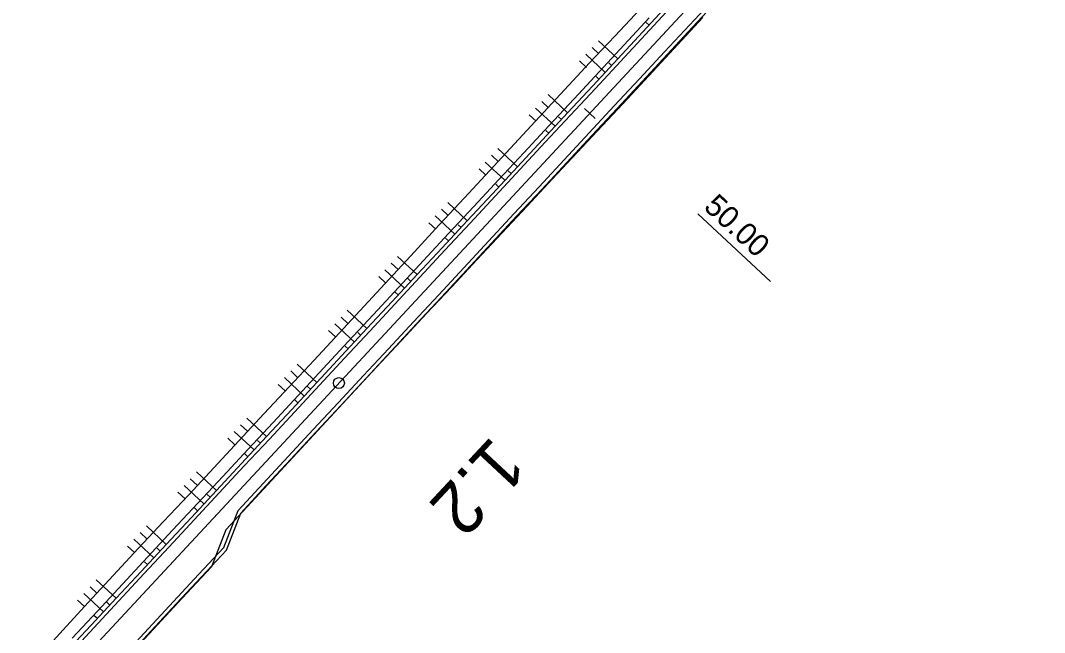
# Model space of a CAD drawing. Extents: x -481645 to -478728, y -1113199 to -1110710.
# Drawn here: x -479136.3 to -478997.3, y -1110940.2 to -1110857.1 of the extents above; entities that cross this region are included whole.
import ezdxf

# ---------------------------------------------------------------- set-up
doc = ezdxf.new("R2010")
doc.units = 0
for name, color, linetype in [('CP14_HATCH_SLOPE_L', 7, 'Continuous'), ('CP1_HECTOMETRY', 7, 'Continuous'), ('O6_HATCH_SLOPE_L', 7, 'Continuous'), ('O6_HATCH_SLOPE_R', 7, 'Continuous'), ('O6_HLBODY', 7, 'Continuous'), ('O6_HRANA_TELESO', 7, 'Continuous'), ('O6_OSA', 7, 'Continuous'), ('O6_VOZOVKA', 7, 'Continuous'), ('O6_ZPEVKRAJ', 7, 'Continuous')]:
    doc.layers.add(name, color=color, linetype=linetype)

msp = doc.modelspace()

# ---------------------------------------------------------------- linework, layer by layer
at = {"layer": 'CP14_HATCH_SLOPE_L'}
for p, q in [((-479047.12, -1110860.26), (-479047.03, -1110860.35)), ((-479047.98, -1110861.18), (-479047.93, -1110861.22)), ((-479047.88, -1110861.27), (-479047.88, -1110861.27)), ((-479049.68, -1110863.01), (-479049.63, -1110863.06)), ((-479049.58, -1110863.1), (-479049.58, -1110863.1)), ((-479048.83, -1110862.09), (-479048.73, -1110862.19)), ((-479053.93, -1110867.58), (-479053.83, -1110867.69)), ((-479054.79, -1110868.5), (-479054.73, -1110868.55)), ((-479054.68, -1110868.6), (-479054.68, -1110868.6)), ((-479056.49, -1110870.33), (-479056.44, -1110870.38)), ((-479055.64, -1110869.42), (-479055.53, -1110869.51)), ((-479056.39, -1110870.43), (-479056.39, -1110870.43)), ((-479061.6, -1110875.82), (-479061.55, -1110875.86)), ((-479061.51, -1110875.9), (-479061.51, -1110875.9)), ((-479060.74, -1110874.91), (-479060.66, -1110874.99)), ((-479062.45, -1110876.74), (-479062.36, -1110876.82)), ((-479063.3, -1110877.65), (-479063.26, -1110877.69)), ((-479063.22, -1110877.73), (-479063.22, -1110877.73)), ((-479067.55, -1110882.23), (-479067.49, -1110882.29)), ((-479069.26, -1110884.06), (-479069.19, -1110884.12)), ((-479068.41, -1110883.15), (-479068.37, -1110883.18)), ((-479068.34, -1110883.21), (-479068.34, -1110883.21)), ((-479070.11, -1110884.98), (-479070.08, -1110885)), ((-479070.05, -1110885.03), (-479070.05, -1110885.03)), ((-479074.36, -1110889.55), (-479074.32, -1110889.6)), ((-479075.22, -1110890.47), (-479075.19, -1110890.49)), ((-479075.17, -1110890.51), (-479075.17, -1110890.51)), ((-479076.92, -1110892.3), (-479076.9, -1110892.32)), ((-479076.88, -1110892.34), (-479076.88, -1110892.34)), ((-479076.07, -1110891.38), (-479076.02, -1110891.43)), ((-479082.03, -1110897.79), (-479082.01, -1110897.8)), ((-479082, -1110897.82), (-479082, -1110897.82)), ((-479081.17, -1110896.88), (-479081.15, -1110896.9)), ((-479082.88, -1110898.71), (-479082.85, -1110898.73)), ((-479083.73, -1110899.62), (-479083.72, -1110899.63)), ((-479083.71, -1110899.64), (-479083.71, -1110899.64)), ((-479088.84, -1110905.11), (-479088.83, -1110905.12)), ((-479088.82, -1110905.13), (-479088.82, -1110905.13)), ((-479087.98, -1110904.2), (-479087.97, -1110904.22)), ((-479089.69, -1110906.03), (-479089.67, -1110906.05)), ((-479090.54, -1110906.95), (-479090.53, -1110906.96)), ((-479090.52, -1110906.97), (-479090.52, -1110906.97)), ((-479094.79, -1110911.52), (-479094.77, -1110911.55)), ((-479096.5, -1110913.35), (-479096.47, -1110913.38)), ((-479095.65, -1110912.44), (-479095.63, -1110912.45)), ((-479095.62, -1110912.47), (-479095.62, -1110912.47)), ((-479097.35, -1110914.27), (-479097.33, -1110914.28)), ((-479097.32, -1110914.3), (-479097.32, -1110914.3)), ((-479101.6, -1110918.84), (-479101.56, -1110918.88)), ((-479102.46, -1110919.76), (-479102.43, -1110919.78)), ((-479102.41, -1110919.8), (-479102.41, -1110919.8)), ((-479104.16, -1110921.59), (-479104.14, -1110921.61)), ((-479104.11, -1110921.63), (-479104.11, -1110921.63)), ((-479103.31, -1110920.68), (-479103.26, -1110920.72)), ((-479108.41, -1110926.17), (-479108.36, -1110926.21)), ((-479109.38, -1110928.68), (-479109.33, -1110928.73)), ((-479108.9, -1110927.42), (-479108.87, -1110927.45)), ((-479108.85, -1110927.47), (-479108.85, -1110927.47)), ((-479109.87, -1110929.94), (-479109.84, -1110929.96)), ((-479109.82, -1110929.98), (-479109.82, -1110929.98)), ((-479113.76, -1110934.85), (-479113.71, -1110934.9)), ((-479115.46, -1110936.68), (-479115.41, -1110936.74)), ((-479114.61, -1110935.77), (-479114.58, -1110935.79)), ((-479114.56, -1110935.82), (-479114.56, -1110935.82)), ((-479116.31, -1110937.6), (-479116.28, -1110937.63)), ((-479116.26, -1110937.65), (-479116.26, -1110937.65))]:
    msp.add_line(p, q, dxfattribs=at)
at = {"layer": 'CP1_HECTOMETRY'}
msp.add_line((-479231.87, -1111055.62), (-478997.26, -1110803.33), dxfattribs=at)
at = {"layer": 'O6_HATCH_SLOPE_L'}
msp.add_circle((-479093.04, -1110906.33), 0.75, dxfattribs=at)
at = {"layer": 'O6_HATCH_SLOPE_R'}
for p, q in [((-479050.93, -1110857.74), (-479051.31, -1110857.38)), ((-479055.18, -1110862.32), (-479057.82, -1110859.86)), ((-479056.88, -1110864.15), (-479059.53, -1110861.69)), ((-479057.75, -1110861.64), (-479058.68, -1110860.77)), ((-479059.45, -1110863.47), (-479060.39, -1110862.6)), ((-479056.03, -1110863.23), (-479056.42, -1110862.87)), ((-479057.74, -1110865.06), (-479058.13, -1110864.7)), ((-479061.99, -1110869.64), (-479064.65, -1110867.17)), ((-479063.69, -1110871.47), (-479066.35, -1110869)), ((-479064.57, -1110868.95), (-479065.5, -1110868.08)), ((-479066.27, -1110870.78), (-479067.21, -1110869.91)), ((-479062.84, -1110870.56), (-479063.24, -1110870.19)), ((-479064.55, -1110872.39), (-479064.94, -1110872.02)), ((-479068.8, -1110876.96), (-479071.46, -1110874.49)), ((-479071.38, -1110876.27), (-479072.31, -1110875.4)), ((-479073.08, -1110878.1), (-479074.02, -1110877.24)), ((-479070.5, -1110878.79), (-479073.17, -1110876.32)), ((-479069.65, -1110877.88), (-479070.05, -1110877.51)), ((-479071.35, -1110879.71), (-479071.75, -1110879.34)), ((-479078.19, -1110883.59), (-479079.12, -1110882.73)), ((-479075.61, -1110884.29), (-479078.27, -1110881.81)), ((-479077.31, -1110886.12), (-479079.98, -1110883.64)), ((-479079.89, -1110885.42), (-479080.83, -1110884.56)), ((-479076.46, -1110885.2), (-479076.86, -1110884.83)), ((-479078.17, -1110887.03), (-479078.56, -1110886.66)), ((-479082.42, -1110891.61), (-479085.08, -1110889.13)), ((-479084.12, -1110893.44), (-479086.79, -1110890.96)), ((-479085, -1110890.91), (-479085.94, -1110890.05)), ((-479086.71, -1110892.74), (-479087.64, -1110891.88)), ((-479083.27, -1110892.52), (-479083.67, -1110892.15)), ((-479084.98, -1110894.35), (-479085.38, -1110893.98)), ((-479089.23, -1110898.93), (-479091.9, -1110896.45)), ((-479091.82, -1110898.23), (-479092.75, -1110897.37)), ((-479093.52, -1110900.06), (-479094.46, -1110899.2)), ((-479090.93, -1110900.76), (-479093.6, -1110898.28)), ((-479090.08, -1110899.85), (-479090.48, -1110899.47)), ((-479091.79, -1110901.68), (-479092.19, -1110901.3)), ((-479096.04, -1110906.26), (-479098.72, -1110903.77)), ((-479098.64, -1110905.55), (-479099.57, -1110904.68)), ((-479100.34, -1110907.38), (-479101.28, -1110906.51)), ((-479097.74, -1110908.09), (-479100.42, -1110905.59)), ((-479096.89, -1110907.17), (-479097.3, -1110906.79)), ((-479098.6, -1110909), (-479099, -1110908.62)), ((-479105.46, -1110912.86), (-479106.39, -1110911.99)), ((-479102.85, -1110913.58), (-479105.54, -1110911.08)), ((-479104.55, -1110915.41), (-479107.24, -1110912.91)), ((-479107.16, -1110914.69), (-479108.1, -1110913.82)), ((-479103.7, -1110914.49), (-479104.11, -1110914.11)), ((-479105.41, -1110916.32), (-479105.81, -1110915.94)), ((-479109.66, -1110920.9), (-479112.36, -1110918.39)), ((-479111.36, -1110922.73), (-479114.06, -1110920.22)), ((-479112.27, -1110920.18), (-479113.21, -1110919.31)), ((-479113.97, -1110922.01), (-479114.91, -1110921.14)), ((-479110.51, -1110921.82), (-479110.92, -1110921.44)), ((-479112.22, -1110923.65), (-479112.62, -1110923.27)), ((-479116.47, -1110928.22), (-479119.17, -1110925.71)), ((-479119.08, -1110927.51), (-479120.02, -1110926.63)), ((-479120.78, -1110929.34), (-479121.72, -1110928.46)), ((-479118.17, -1110930.05), (-479120.87, -1110927.54)), ((-479117.32, -1110929.14), (-479117.73, -1110928.76)), ((-479119.02, -1110930.97), (-479119.43, -1110930.59)), ((-479125.88, -1110934.84), (-479126.82, -1110933.97)), ((-479123.28, -1110935.55), (-479125.97, -1110933.04)), ((-479124.98, -1110937.38), (-479127.66, -1110934.89)), ((-479127.58, -1110936.67), (-479128.51, -1110935.81)), ((-479124.13, -1110936.46), (-479124.54, -1110936.09)), ((-479125.83, -1110938.29), (-479126.24, -1110937.92))]:
    msp.add_line(p, q, dxfattribs=at)
at = {"layer": 'O6_HLBODY'}
for p, q in [((-479058.26, -1110870.4), (-479059.72, -1110869.03)), ((-479044.34, -1110883.33), (-479034.46, -1110892.53))]:
    msp.add_line(p, q, dxfattribs=at)
at = {"layer": 'O6_HRANA_TELESO'}
for p, q in [((-479054.31, -1110860.41), (-479050.91, -1110856.74)), ((-479057.72, -1110864.07), (-479054.31, -1110860.41)), ((-479061.12, -1110867.73), (-479057.72, -1110864.07)), ((-479064.53, -1110871.39), (-479061.12, -1110867.73)), ((-479067.93, -1110875.05), (-479064.53, -1110871.39)), ((-479071.34, -1110878.71), (-479067.93, -1110875.05)), ((-479074.74, -1110882.37), (-479071.34, -1110878.71)), ((-479078.15, -1110886.03), (-479074.74, -1110882.37)), ((-479081.55, -1110889.7), (-479078.15, -1110886.03)), ((-479084.96, -1110893.36), (-479081.55, -1110889.7)), ((-479088.36, -1110897.02), (-479084.96, -1110893.36)), ((-479091.77, -1110900.68), (-479088.36, -1110897.02)), ((-479095.17, -1110904.34), (-479091.77, -1110900.68)), ((-479098.58, -1110908), (-479095.17, -1110904.34)), ((-479101.98, -1110911.67), (-479098.58, -1110908)), ((-479105.39, -1110915.33), (-479101.98, -1110911.67)), ((-479108.79, -1110918.99), (-479105.39, -1110915.33)), ((-479112.2, -1110922.65), (-479108.79, -1110918.99)), ((-479115.61, -1110926.3), (-479112.2, -1110922.65)), ((-479119.02, -1110929.97), (-479115.61, -1110926.3)), ((-479122.42, -1110933.63), (-479119.02, -1110929.97)), ((-479125.83, -1110937.29), (-479122.42, -1110933.63)), ((-479129.23, -1110940.95), (-479125.83, -1110937.29))]:
    msp.add_line(p, q, dxfattribs=at)
at = {"layer": 'O6_OSA'}
for p, q in [((-479055.59, -1110859.22), (-479052.16, -1110855.58)), ((-479047.03, -1110860.35), (-479043.62, -1110856.69)), ((-479059.02, -1110862.86), (-479055.59, -1110859.22)), ((-479050.43, -1110864.02), (-479047.03, -1110860.35)), ((-479062.42, -1110866.52), (-479059.02, -1110862.86)), ((-479053.83, -1110867.69), (-479050.43, -1110864.02)), ((-479065.82, -1110870.19), (-479062.42, -1110866.52)), ((-479057.24, -1110871.34), (-479053.83, -1110867.69)), ((-479069.21, -1110873.86), (-479065.82, -1110870.19)), ((-479060.66, -1110874.99), (-479057.24, -1110871.34)), ((-479072.61, -1110877.53), (-479069.21, -1110873.86)), ((-479064.07, -1110878.64), (-479060.66, -1110874.99)), ((-479076.01, -1110881.2), (-479072.61, -1110877.53)), ((-479067.49, -1110882.29), (-479064.07, -1110878.64)), ((-479079.41, -1110884.86), (-479076.01, -1110881.2)), ((-479070.9, -1110885.95), (-479067.49, -1110882.29)), ((-479082.8, -1110888.53), (-479079.41, -1110884.86)), ((-479074.32, -1110889.6), (-479070.9, -1110885.95)), ((-479086.2, -1110892.2), (-479082.8, -1110888.53)), ((-479077.73, -1110893.25), (-479074.32, -1110889.6)), ((-479089.6, -1110895.87), (-479086.2, -1110892.2)), ((-479081.15, -1110896.9), (-479077.73, -1110893.25)), ((-479093, -1110899.53), (-479089.6, -1110895.87)), ((-479084.56, -1110900.55), (-479081.15, -1110896.9)), ((-479096.41, -1110903.2), (-479093, -1110899.53)), ((-479087.97, -1110904.22), (-479084.56, -1110900.55)), ((-479099.81, -1110906.86), (-479096.41, -1110903.2)), ((-479091.37, -1110907.88), (-479087.97, -1110904.22)), ((-479103.21, -1110910.52), (-479099.81, -1110906.86)), ((-479094.77, -1110911.55), (-479091.37, -1110907.88)), ((-479106.61, -1110914.19), (-479103.21, -1110910.52)), ((-479098.17, -1110915.22), (-479094.77, -1110911.55)), ((-479110.02, -1110917.85), (-479106.61, -1110914.19)), ((-479101.56, -1110918.88), (-479098.17, -1110915.22)), ((-479113.43, -1110921.5), (-479110.02, -1110917.85)), ((-479104.96, -1110922.55), (-479101.56, -1110918.88)), ((-479116.86, -1110925.14), (-479113.43, -1110921.5)), ((-479108.36, -1110926.21), (-479104.96, -1110922.55)), ((-479120.27, -1110928.79), (-479116.86, -1110925.14)), ((-479110.3, -1110931.24), (-479108.36, -1110926.21)), ((-479123.68, -1110932.45), (-479120.27, -1110928.79)), ((-479113.71, -1110934.9), (-479110.3, -1110931.24)), ((-479127.07, -1110936.13), (-479123.68, -1110932.45)), ((-479117.11, -1110938.57), (-479113.71, -1110934.9)), ((-479130.46, -1110939.81), (-479127.07, -1110936.13)), ((-479133.82, -1110943.51), (-479130.46, -1110939.81)), ((-479120.5, -1110942.24), (-479117.11, -1110938.57))]:
    msp.add_line(p, q, dxfattribs=at)
at = {"layer": 'O6_VOZOVKA'}
for p, q in [((-479045.44, -1110857.72), (-479042.04, -1110854.06)), ((-479051.41, -1110859), (-479048.01, -1110855.33)), ((-479048.85, -1110861.38), (-479045.44, -1110857.72)), ((-479054.82, -1110862.66), (-479051.41, -1110859)), ((-479052.25, -1110865.04), (-479048.85, -1110861.38)), ((-479058.22, -1110866.32), (-479054.82, -1110862.66)), ((-479055.66, -1110868.7), (-479052.25, -1110865.04)), ((-479061.63, -1110869.98), (-479058.22, -1110866.32)), ((-479059.06, -1110872.36), (-479055.66, -1110868.7)), ((-479065.03, -1110873.64), (-479061.63, -1110869.98)), ((-479062.47, -1110876.03), (-479059.06, -1110872.36)), ((-479068.44, -1110877.3), (-479065.03, -1110873.64)), ((-479071.84, -1110880.97), (-479068.44, -1110877.3)), ((-479065.87, -1110879.69), (-479062.47, -1110876.03)), ((-479069.28, -1110883.35), (-479065.87, -1110879.69)), ((-479075.24, -1110884.63), (-479071.84, -1110880.97)), ((-479072.68, -1110887.01), (-479069.28, -1110883.35)), ((-479078.65, -1110888.29), (-479075.24, -1110884.63)), ((-479076.09, -1110890.67), (-479072.68, -1110887.01)), ((-479082.05, -1110891.95), (-479078.65, -1110888.29)), ((-479079.49, -1110894.33), (-479076.09, -1110890.67)), ((-479085.46, -1110895.61), (-479082.05, -1110891.95)), ((-479082.9, -1110898), (-479079.49, -1110894.33)), ((-479088.86, -1110899.27), (-479085.46, -1110895.61)), ((-479086.3, -1110901.66), (-479082.9, -1110898)), ((-479092.27, -1110902.93), (-479088.86, -1110899.27)), ((-479089.71, -1110905.32), (-479086.3, -1110901.66)), ((-479095.67, -1110906.6), (-479092.27, -1110902.93)), ((-479093.11, -1110908.98), (-479089.71, -1110905.32)), ((-479099.08, -1110910.26), (-479095.67, -1110906.6)), ((-479096.52, -1110912.64), (-479093.11, -1110908.98)), ((-479102.48, -1110913.92), (-479099.08, -1110910.26)), ((-479099.92, -1110916.3), (-479096.52, -1110912.64)), ((-479105.89, -1110917.58), (-479102.48, -1110913.92)), ((-479109.29, -1110921.24), (-479105.89, -1110917.58)), ((-479103.33, -1110919.96), (-479099.92, -1110916.3)), ((-479106.73, -1110923.62), (-479103.33, -1110919.96)), ((-479112.7, -1110924.9), (-479109.29, -1110921.24)), ((-479108.67, -1110928.65), (-479106.73, -1110923.62)), ((-479116.1, -1110928.56), (-479112.7, -1110924.9)), ((-479119.51, -1110932.23), (-479116.1, -1110928.56)), ((-479112.08, -1110932.31), (-479108.67, -1110928.65)), ((-479122.91, -1110935.89), (-479119.51, -1110932.23)), ((-479115.48, -1110935.97), (-479112.08, -1110932.31)), ((-479126.32, -1110939.55), (-479122.91, -1110935.89)), ((-479118.89, -1110939.63), (-479115.48, -1110935.97)), ((-479129.72, -1110943.21), (-479126.32, -1110939.55)), ((-479122.29, -1110943.29), (-479118.89, -1110939.63))]:
    msp.add_line(p, q, dxfattribs=at)
at = {"layer": 'O6_ZPEVKRAJ'}
for p, q in [((-479051.78, -1110858.66), (-479048.37, -1110854.99)), ((-479045.08, -1110858.06), (-479041.67, -1110854.4)), ((-479055.18, -1110862.32), (-479051.78, -1110858.66)), ((-479048.48, -1110861.72), (-479045.08, -1110858.06)), ((-479051.89, -1110865.38), (-479048.48, -1110861.72)), ((-479058.59, -1110865.98), (-479055.18, -1110862.32)), ((-479061.99, -1110869.64), (-479058.59, -1110865.98)), ((-479055.29, -1110869.04), (-479051.89, -1110865.38)), ((-479065.4, -1110873.3), (-479061.99, -1110869.64)), ((-479058.7, -1110872.71), (-479055.29, -1110869.04)), ((-479062.1, -1110876.37), (-479058.7, -1110872.71)), ((-479068.8, -1110876.96), (-479065.4, -1110873.3)), ((-479072.21, -1110880.62), (-479068.8, -1110876.96)), ((-479065.51, -1110880.03), (-479062.1, -1110876.37)), ((-479068.91, -1110883.69), (-479065.51, -1110880.03)), ((-479075.61, -1110884.29), (-479072.21, -1110880.62)), ((-479079.02, -1110887.95), (-479075.61, -1110884.29)), ((-479072.32, -1110887.35), (-479068.91, -1110883.69)), ((-479082.42, -1110891.61), (-479079.02, -1110887.95)), ((-479075.72, -1110891.01), (-479072.32, -1110887.35)), ((-479079.13, -1110894.67), (-479075.72, -1110891.01)), ((-479085.83, -1110895.27), (-479082.42, -1110891.61)), ((-479089.23, -1110898.93), (-479085.83, -1110895.27)), ((-479082.53, -1110898.33), (-479079.13, -1110894.67)), ((-479092.64, -1110902.59), (-479089.23, -1110898.93)), ((-479085.94, -1110902), (-479082.53, -1110898.33)), ((-479089.34, -1110905.66), (-479085.94, -1110902)), ((-479096.04, -1110906.26), (-479092.64, -1110902.59)), ((-479099.45, -1110909.92), (-479096.04, -1110906.26)), ((-479092.75, -1110909.32), (-479089.34, -1110905.66)), ((-479096.15, -1110912.98), (-479092.75, -1110909.32)), ((-479102.85, -1110913.58), (-479099.45, -1110909.92)), ((-479099.56, -1110916.64), (-479096.15, -1110912.98)), ((-479106.26, -1110917.24), (-479102.85, -1110913.58)), ((-479109.66, -1110920.9), (-479106.26, -1110917.24)), ((-479102.96, -1110920.3), (-479099.56, -1110916.64)), ((-479106.37, -1110923.97), (-479102.96, -1110920.3)), ((-479113.07, -1110924.56), (-479109.66, -1110920.9)), ((-479116.47, -1110928.22), (-479113.07, -1110924.56)), ((-479108.31, -1110928.99), (-479106.37, -1110923.97)), ((-479119.88, -1110931.89), (-479116.47, -1110928.22)), ((-479111.71, -1110932.65), (-479108.31, -1110928.99)), ((-479123.28, -1110935.55), (-479119.88, -1110931.89)), ((-479115.12, -1110936.31), (-479111.71, -1110932.65)), ((-479126.69, -1110939.21), (-479123.28, -1110935.55)), ((-479118.52, -1110939.97), (-479115.12, -1110936.31)), ((-479130.09, -1110942.87), (-479126.69, -1110939.21)), ((-479121.93, -1110943.64), (-479118.52, -1110939.97))]:
    msp.add_line(p, q, dxfattribs=at)

# ---------------------------------------------------------------- texts
at = {"layer": 'O6_HATCH_SLOPE_L'}
msp.add_text('1.2', height=7, rotation=227.0337, dxfattribs=at).set_placement((-479072.23, -1110913.33))
at = {"layer": 'O6_HLBODY'}
msp.add_text('50.00', height=2.999, rotation=317.0793, dxfattribs=at).set_placement((-479043.66, -1110882.6))

doc.saveas('drawing.dxf')
